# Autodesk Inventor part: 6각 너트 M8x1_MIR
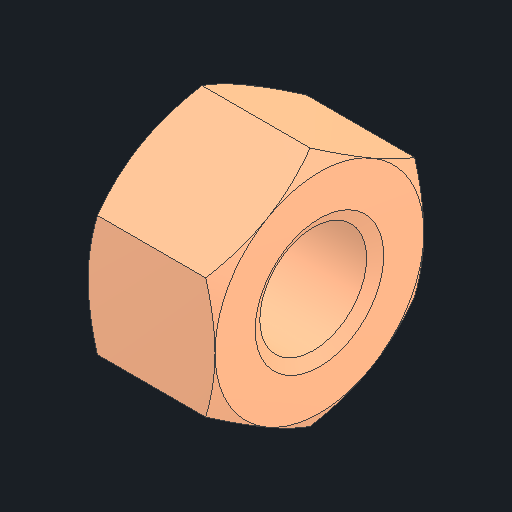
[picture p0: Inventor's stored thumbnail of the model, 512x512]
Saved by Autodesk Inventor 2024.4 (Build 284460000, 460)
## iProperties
Created: 2025-10
Part Number: 6각 너트 M8x1_MIR
Material: 강철, 연강
Description: 6각 너트 및 6각 가는 너트
Document SubType Name: Modeling
Designer: user
Density: 7.85 g/cm^3
Appearance: 기본값
Author: jhkim
Sending System: Autodesk Inventor 2026
Preprocessor: ST-DEVELOPER v20.1
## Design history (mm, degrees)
derived "6각 너트 M8x1.ipt"
feature "솔리드1::6각 너트 M8x1.ipt" dims "d0" = 10
tag "피쳐 태그1"
node "솔리드1"
